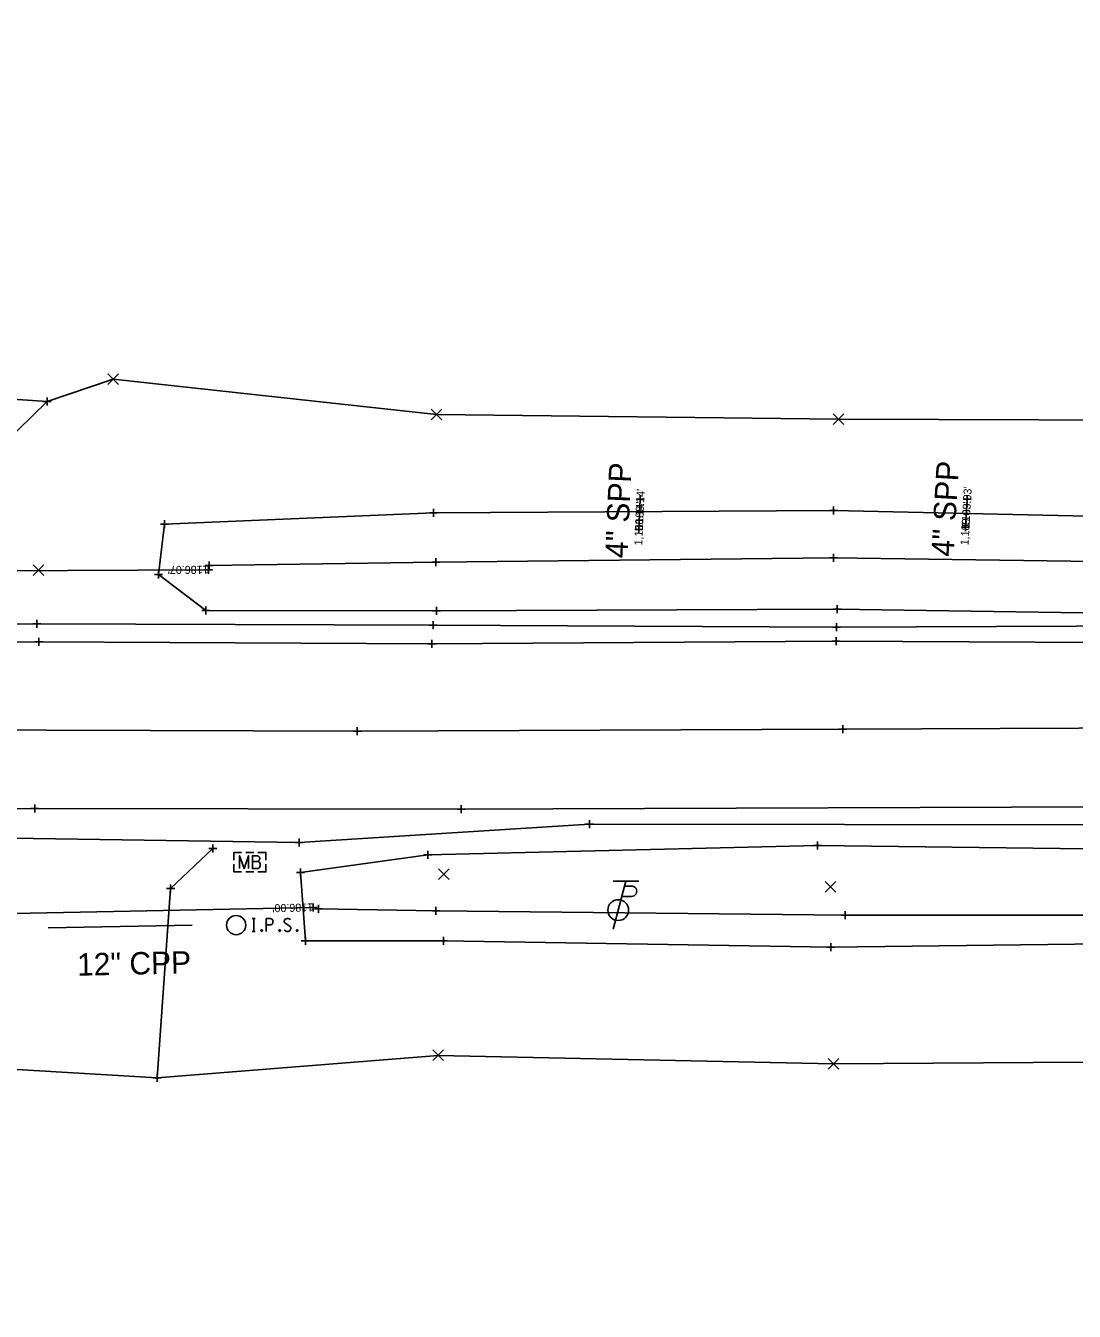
# Model space of a CAD drawing. Extents: x 2319153 to 2321514, y 575338 to 575500.
# Drawn here: x 2320961.9 to 2321092.9, y 575339 to 575499.6 of the extents above; entities that cross this region are included whole.
import ezdxf

# ---------------------------------------------------------------- set-up
doc = ezdxf.new("R2010")
doc.units = 0
for name, color, linetype in [('Default', 7, 'Continuous'), ('DR_X_Ditch', 7, 'Continuous'), ('DR_X_Elev_Flow', 7, 'Continuous'), ('DR_X_Storm_Sewer', 7, 'Continuous'), ('DR_X_Text', 7, 'Continuous'), ('PV_X_COP', 7, 'Continuous'), ('PV_X_Driveway', 7, 'Continuous'), ('PV_X_EOP', 7, 'Continuous'), ('PV_X_Shoulder', 7, 'Continuous'), ('RD_X_Cells', 7, 'Continuous'), ('SC_Scratch1', 7, 'Continuous'), ('SV_P_Mon_Cells_Set', 7, 'Continuous'), ('SV_X_Break_Lines', 7, 'Continuous'), ('SV_X_Random_Point', 7, 'Continuous'), ('SV_X_Shot_Marker', 7, 'Continuous'), ('SV_X_Terrain_Boundary', 7, 'Continuous'), ('UT_X_Misc_Cells', 7, 'Continuous')]:
    doc.layers.add(name, color=color, linetype=linetype)

msp = doc.modelspace()

# ---------------------------------------------------------------- linework, layer by layer
at = {"layer": 'Default'}
for p, q in [((2321038.48, 575436.66), (2321038.48, 575436.66)), ((2321079.27, 575436.97), (2321079.27, 575436.97))]:
    msp.add_line(p, q, dxfattribs=at)
at = {"layer": 'DR_X_Ditch'}
for points in [[(2320984.82, 575432.18), (2321013.13, 575432.58), (2321062.77, 575433.12), (2321113.21, 575432.44), (2321157.3, 575431.05)], [(2321201.56, 575392.03), (2321163.08, 575389.89), (2321113.15, 575388.46), (2321064.26, 575388.47), (2321013.1, 575389.02), (2320998.47, 575389.29)]]:
    msp.add_lwpolyline(points, dxfattribs=at)
at = {"layer": 'DR_X_Elev_Flow'}
for p, q in [((2321038.15, 575440.47), (2321039.15, 575440.47)), ((2321038.65, 575440.97), (2321038.65, 575439.97)), ((2321038.65, 575440.47), (2321038.65, 575440.47)), ((2321078.98, 575440.48), (2321079.98, 575440.48)), ((2321079.48, 575440.98), (2321079.48, 575439.98)), ((2321079.48, 575440.48), (2321079.48, 575440.48)), ((2321037.98, 575436.66), (2321038.98, 575436.66)), ((2321038.48, 575437.16), (2321038.48, 575436.16)), ((2321038.48, 575436.66), (2321038.48, 575436.66)), ((2321078.77, 575436.97), (2321079.77, 575436.97)), ((2321079.27, 575437.47), (2321079.27, 575436.47)), ((2321079.27, 575436.97), (2321079.27, 575436.97)), ((2320984.23, 575431.64), (2320985.23, 575431.64)), ((2320984.73, 575432.14), (2320984.73, 575431.14)), ((2320984.73, 575431.64), (2320984.73, 575431.64)), ((2320997.8, 575389.95), (2320997.8, 575388.95)), ((2320997.3, 575389.45), (2320998.3, 575389.45)), ((2320997.8, 575389.45), (2320997.8, 575389.45))]:
    msp.add_line(p, q, dxfattribs=at)
at = {"layer": 'DR_X_Storm_Sewer'}
for p, q in [((2321038.48, 575436.66), (2321038.65, 575440.47)), ((2321079.27, 575436.97), (2321079.48, 575440.48)), ((2320984.73, 575431.64), (2320820.1, 575430.96)), ((2320997.8, 575389.45), (2320953.53, 575388.55))]:
    msp.add_line(p, q, dxfattribs=at)
at = {"layer": 'DR_X_Text'}
msp.add_line((2320964.71, 575386.88), (2320982.7, 575387.24), dxfattribs=at)
at = {"layer": 'PV_X_COP'}
msp.add_lwpolyline([(2320664.58, 575411.98), (2320714.9, 575412.38), (2320764.67, 575412.55), (2320812.81, 575411.44), (2320863.71, 575412.31), (2320912.72, 575411.78), (2321003.29, 575411.48), (2321063.97, 575411.74), (2321113.08, 575411.94), (2321163.31, 575411.56), (2321212.82, 575411.61), (2321262.91, 575411.78), (2321313.37, 575411.56), (2321362.17, 575411.58), (2321412.59, 575412.78), (2321463.09, 575413.59), (2321512.4, 575413.87)], dxfattribs=at)
at = {"layer": 'PV_X_Driveway'}
for points in [[(2320964.59, 575452.67), (2320949.93, 575438.38), (2320946.04, 575432.42), (2320950.26, 575425.38)], [(2320978.33, 575368.17), (2320980, 575391.82), (2320985.27, 575396.83)]]:
    msp.add_lwpolyline(points, dxfattribs=at)
at = {"layer": 'PV_X_EOP'}
for points in [[(2320664.7, 575422.48), (2320715.11, 575422.41), (2320765.04, 575422.04), (2320813.73, 575422.51), (2320875.77, 575422.41), (2320913.27, 575422.56), (2320963.52, 575422.63), (2321012.62, 575422.4), (2321063.13, 575422.74), (2321112.87, 575422.46), (2321162.94, 575422.5), (2321212.67, 575422.22), (2321263.07, 575422.64), (2321312.9, 575422.52), (2321362.03, 575422.99), (2321412.61, 575423.24), (2321462.61, 575423.66), (2321512.13, 575424.2)], [(2321512.27, 575403.63), (2321462.49, 575403.2), (2321412.87, 575402.74), (2321362.69, 575401.87), (2321312.5, 575402.02), (2321262.43, 575401.63), (2321211.98, 575401.55), (2321107.93, 575402.06), (2321016.27, 575401.73), (2320963.04, 575401.8), (2320913.34, 575401.45), (2320862.76, 575402.1), (2320813.85, 575401.67), (2320764.22, 575401.77), (2320714.4, 575401.87), (2320664.35, 575401.67)]]:
    msp.add_lwpolyline(points, dxfattribs=at)
at = {"layer": 'PV_X_Shoulder'}
for points in [[(2320664.52, 575424.33), (2320715.19, 575424.71), (2320764.98, 575424.15), (2320814.14, 575424.35), (2320863.42, 575424.12), (2320913.2, 575424.6), (2320963.28, 575424.88), (2321012.77, 575424.72), (2321063.18, 575424.45), (2321113.13, 575424.68), (2321162.73, 575424.41), (2321212.81, 575424.31), (2321262.9, 575424.09), (2321312.43, 575424.58), (2321362.34, 575425.06), (2321412.6, 575426.1), (2321462.14, 575426.29), (2321512.24, 575426.46)], [(2321513.03, 575401.02), (2321462.24, 575401.09), (2321412.23, 575401.08), (2321362.25, 575400.75), (2321312.5, 575400.39), (2321262.08, 575400.08), (2321212.3, 575399.81), (2321130.87, 575399.59), (2321095.99, 575399.76), (2321032.33, 575399.84), (2320996.03, 575397.56), (2320957.29, 575398.14), (2320912.73, 575400.28), (2320862.68, 575400.51), (2320815.54, 575400.3), (2320764.25, 575400.14), (2320714.58, 575400.4), (2320664.56, 575400.05)]]:
    msp.add_lwpolyline(points, dxfattribs=at)
at = {"layer": 'RD_X_Cells'}
for p, q in [((2320989.38, 575396.33), (2320990.38, 575396.33)), ((2320989.89, 575395.11), (2320989.89, 575395.11)), ((2320989.38, 575393.89), (2320990.38, 575393.89))]:
    msp.add_line(p, q, dxfattribs=at)
for points in [[(2320987.89, 575395.36), (2320987.89, 575396.33), (2320988.86, 575396.33)], [(2320990.9, 575396.33), (2320991.89, 575396.33), (2320991.89, 575395.36)], [(2320988.86, 575393.89), (2320987.89, 575393.89), (2320987.89, 575394.86)], [(2320988.6, 575394.31), (2320988.6, 575395.91), (2320989.18, 575394.31), (2320989.73, 575395.91), (2320989.73, 575394.31)], [(2320990.91, 575395.18), (2320990.98, 575395.24), (2320991.01, 575395.28), (2320991.04, 575395.32), (2320991.05, 575395.34), (2320991.08, 575395.39), (2320991.09, 575395.43), (2320991.12, 575395.52), (2320991.12, 575395.55), (2320991.12, 575395.61), (2320991.1, 575395.68), (2320991.08, 575395.74), (2320991.04, 575395.79), (2320990.98, 575395.84), (2320990.93, 575395.87), (2320990.9, 575395.88), (2320990.84, 575395.91), (2320990.22, 575395.91), (2320990.22, 575394.31), (2320990.91, 575394.31), (2320991, 575394.36), (2320991.08, 575394.42), (2320991.14, 575394.52), (2320991.18, 575394.63), (2320991.19, 575394.75), (2320991.19, 575394.82), (2320991.17, 575394.9), (2320991.12, 575395.01), (2320991.05, 575395.09), (2320990.91, 575395.18), (2320990.22, 575395.18)], [(2320991.89, 575394.86), (2320991.89, 575393.89), (2320990.9, 575393.89)]]:
    msp.add_lwpolyline(points, dxfattribs=at)
at = {"layer": 'SV_P_Mon_Cells_Set'}
for points in [[(2320990.19, 575388.05), (2320990.55, 575388.05)], [(2320990.37, 575386.45), (2320990.37, 575388.05)], [(2320991.94, 575386.45), (2320991.94, 575388.05), (2320992.47, 575388.05), (2320992.52, 575388.03), (2320992.6, 575388.01), (2320992.63, 575387.98), (2320992.66, 575387.96), (2320992.71, 575387.89), (2320992.74, 575387.83), (2320992.76, 575387.73), (2320992.76, 575387.58), (2320992.75, 575387.53), (2320992.73, 575387.45), (2320992.69, 575387.37), (2320992.64, 575387.33), (2320992.61, 575387.3), (2320992.55, 575387.28), (2320992.47, 575387.26), (2320991.94, 575387.26)], [(2320994.95, 575387.93), (2320994.92, 575387.96), (2320994.89, 575387.98), (2320994.79, 575388.02), (2320994.67, 575388.05), (2320994.58, 575388.05), (2320994.55, 575388.05), (2320994.41, 575388.01), (2320994.28, 575387.93), (2320994.21, 575387.83), (2320994.19, 575387.73), (2320994.19, 575387.66), (2320994.21, 575387.55), (2320994.3, 575387.47), (2320994.9, 575387.09), (2320994.96, 575387.04), (2320994.98, 575386.99), (2320995, 575386.91), (2320995, 575386.84), (2320994.99, 575386.76), (2320994.98, 575386.71), (2320994.96, 575386.65), (2320994.93, 575386.6), (2320994.91, 575386.56), (2320994.88, 575386.52), (2320994.85, 575386.5), (2320994.8, 575386.47), (2320994.77, 575386.46), (2320994.67, 575386.45), (2320994.52, 575386.45), (2320994.42, 575386.47), (2320994.27, 575386.56), (2320994.19, 575386.64)], [(2320990.19, 575386.45), (2320990.55, 575386.45)], [(2320991.33, 575386.66), (2320991.39, 575386.66), (2320991.42, 575386.64), (2320991.45, 575386.58), (2320991.45, 575386.52), (2320991.42, 575386.47), (2320991.39, 575386.45), (2320991.33, 575386.45), (2320991.3, 575386.47), (2320991.26, 575386.52), (2320991.26, 575386.58), (2320991.3, 575386.64), (2320991.33, 575386.66)], [(2320993.58, 575386.66), (2320993.63, 575386.66), (2320993.67, 575386.64), (2320993.7, 575386.58), (2320993.7, 575386.52), (2320993.67, 575386.47), (2320993.63, 575386.45), (2320993.58, 575386.45), (2320993.55, 575386.47), (2320993.51, 575386.52), (2320993.51, 575386.58), (2320993.55, 575386.64), (2320993.58, 575386.66)], [(2320995.76, 575386.66), (2320995.82, 575386.66), (2320995.85, 575386.64), (2320995.88, 575386.58), (2320995.88, 575386.52), (2320995.85, 575386.47), (2320995.82, 575386.45), (2320995.76, 575386.45), (2320995.73, 575386.47), (2320995.7, 575386.52), (2320995.7, 575386.58), (2320995.73, 575386.64), (2320995.76, 575386.66)]]:
    msp.add_lwpolyline(points, dxfattribs=at)
msp.add_circle((2320988.18, 575387.24), 1.2, dxfattribs=at)
at = {"layer": 'SV_X_Break_Lines'}
msp.add_lwpolyline([(2321159.99, 575428.63), (2321160.35, 575434.67), (2321113.2, 575437.94), (2321062.77, 575439.07), (2321012.82, 575438.75), (2320979.25, 575437.35), (2320978.5, 575431.05), (2320984.41, 575426.56), (2321013.21, 575426.53), (2321063.26, 575426.7), (2321113.51, 575425.96), (2321155.53, 575426.35)], close=True, dxfattribs=at)
msp.add_lwpolyline([(2321213.73, 575398.49), (2321160.8, 575396.95), (2321111.27, 575396.57), (2321060.79, 575397.2), (2321012.12, 575396.01), (2320996.2, 575393.81), (2320996.82, 575385.28), (2321014.07, 575385.28), (2321062.46, 575384.49), (2321113.23, 575385.1), (2321161.97, 575386.37), (2321201.76, 575388.95)], dxfattribs=at)
at = {"layer": 'SV_X_Random_Point'}
for p, q in [((2320972.16, 575454.8), (2320973.49, 575456.13)), ((2320972.16, 575456.13), (2320973.49, 575454.8)), ((2321012.53, 575450.36), (2321013.86, 575451.7)), ((2321012.53, 575451.7), (2321013.86, 575450.36)), ((2321062.73, 575449.78), (2321064.06, 575451.12)), ((2321062.73, 575451.12), (2321064.06, 575449.78)), ((2320962.83, 575430.91), (2320964.17, 575432.24)), ((2320962.83, 575432.24), (2320964.17, 575430.91)), ((2321013.47, 575392.95), (2321014.8, 575394.29)), ((2321013.47, 575394.29), (2321014.8, 575392.95)), ((2321061.73, 575391.37), (2321063.07, 575392.7)), ((2321061.73, 575392.7), (2321063.07, 575391.37)), ((2321012.73, 575370.3), (2321014.07, 575371.63)), ((2321012.73, 575371.63), (2321014.07, 575370.3)), ((2321062.13, 575369.25), (2321063.47, 575370.58)), ((2321062.13, 575370.58), (2321063.47, 575369.25))]:
    msp.add_line(p, q, dxfattribs=at)
at = {"layer": 'SV_X_Shot_Marker'}
for p, q in [((2320964.09, 575452.67), (2320965.09, 575452.67)), ((2320964.59, 575453.17), (2320964.59, 575452.17)), ((2320964.59, 575452.67), (2320964.59, 575452.67)), ((2321062.77, 575439.57), (2321062.77, 575438.57)), ((2320979.25, 575437.85), (2320979.25, 575436.85)), ((2321012.32, 575438.75), (2321013.32, 575438.75)), ((2321012.82, 575439.25), (2321012.82, 575438.25)), ((2321012.82, 575438.75), (2321012.82, 575438.75)), ((2321062.27, 575439.07), (2321063.27, 575439.07)), ((2321062.77, 575439.07), (2321062.77, 575439.07)), ((2320978.75, 575437.35), (2320979.75, 575437.35)), ((2320979.25, 575437.35), (2320979.25, 575437.35)), ((2321013.13, 575433.08), (2321013.13, 575432.08)), ((2321062.27, 575433.12), (2321063.27, 575433.12)), ((2321062.77, 575433.62), (2321062.77, 575432.62)), ((2321062.77, 575433.12), (2321062.77, 575433.12)), ((2320978.5, 575431.55), (2320978.5, 575430.55)), ((2320984.32, 575432.18), (2320985.32, 575432.18)), ((2320984.82, 575432.68), (2320984.82, 575431.68)), ((2320984.82, 575432.18), (2320984.82, 575432.18)), ((2321012.63, 575432.58), (2321013.63, 575432.58)), ((2321013.13, 575432.58), (2321013.13, 575432.58)), ((2320978, 575431.05), (2320979, 575431.05)), ((2320978.5, 575431.05), (2320978.5, 575431.05)), ((2320984.41, 575427.06), (2320984.41, 575426.06)), ((2321013.21, 575427.03), (2321013.21, 575426.03)), ((2321062.76, 575426.7), (2321063.76, 575426.7)), ((2321063.26, 575427.2), (2321063.26, 575426.2)), ((2321063.26, 575426.7), (2321063.26, 575426.7)), ((2320963.28, 575425.38), (2320963.28, 575424.38)), ((2320983.91, 575426.56), (2320984.91, 575426.56)), ((2320984.41, 575426.56), (2320984.41, 575426.56)), ((2321012.71, 575426.53), (2321013.71, 575426.53)), ((2321012.77, 575425.22), (2321012.77, 575424.22)), ((2321013.21, 575426.53), (2321013.21, 575426.53)), ((2320962.78, 575424.88), (2320963.78, 575424.88)), ((2320963.28, 575424.88), (2320963.28, 575424.88)), ((2321012.27, 575424.72), (2321013.27, 575424.72)), ((2321012.77, 575424.72), (2321012.77, 575424.72)), ((2321062.68, 575424.45), (2321063.68, 575424.45)), ((2321063.18, 575424.95), (2321063.18, 575423.95)), ((2321063.18, 575424.45), (2321063.18, 575424.45)), ((2320963.02, 575422.63), (2320964.02, 575422.63)), ((2320963.52, 575423.13), (2320963.52, 575422.13)), ((2320963.52, 575422.63), (2320963.52, 575422.63)), ((2321012.12, 575422.4), (2321013.12, 575422.4)), ((2321012.62, 575422.9), (2321012.62, 575421.9)), ((2321012.62, 575422.4), (2321012.62, 575422.4)), ((2321062.63, 575422.74), (2321063.63, 575422.74)), ((2321063.13, 575423.24), (2321063.13, 575422.24)), ((2321063.13, 575422.74), (2321063.13, 575422.74)), ((2321063.97, 575412.24), (2321063.97, 575411.24)), ((2321002.79, 575411.48), (2321003.79, 575411.48)), ((2321003.29, 575411.98), (2321003.29, 575410.98)), ((2321003.29, 575411.48), (2321003.29, 575411.48)), ((2321063.47, 575411.74), (2321064.47, 575411.74)), ((2321063.97, 575411.74), (2321063.97, 575411.74)), ((2320962.54, 575401.8), (2320963.54, 575401.8)), ((2320963.04, 575402.3), (2320963.04, 575401.3)), ((2320963.04, 575401.8), (2320963.04, 575401.8)), ((2321015.77, 575401.73), (2321016.77, 575401.73)), ((2321016.27, 575402.23), (2321016.27, 575401.23)), ((2321016.27, 575401.73), (2321016.27, 575401.73)), ((2321031.83, 575399.84), (2321032.83, 575399.84)), ((2321032.33, 575400.34), (2321032.33, 575399.34)), ((2321032.33, 575399.84), (2321032.33, 575399.84)), ((2320996.03, 575398.06), (2320996.03, 575397.06)), ((2321060.79, 575397.7), (2321060.79, 575396.7)), ((2320984.77, 575396.83), (2320985.77, 575396.83)), ((2320985.27, 575397.33), (2320985.27, 575396.33)), ((2320985.27, 575396.83), (2320985.27, 575396.83)), ((2320995.53, 575397.56), (2320996.53, 575397.56)), ((2320996.03, 575397.56), (2320996.03, 575397.56)), ((2321012.12, 575396.51), (2321012.12, 575395.51)), ((2321060.29, 575397.2), (2321061.29, 575397.2)), ((2321060.79, 575397.2), (2321060.79, 575397.2)), ((2321011.62, 575396.01), (2321012.62, 575396.01)), ((2321012.12, 575396.01), (2321012.12, 575396.01)), ((2320995.7, 575393.81), (2320996.7, 575393.81)), ((2320996.2, 575394.31), (2320996.2, 575393.31)), ((2320996.2, 575393.81), (2320996.2, 575393.81)), ((2320979.5, 575391.82), (2320980.5, 575391.82)), ((2320980, 575392.32), (2320980, 575391.32)), ((2320980, 575391.82), (2320980, 575391.82)), ((2320998.47, 575389.79), (2320998.47, 575388.79)), ((2320997.97, 575389.29), (2320998.97, 575389.29)), ((2320998.47, 575389.29), (2320998.47, 575389.29)), ((2321012.6, 575389.02), (2321013.6, 575389.02)), ((2321013.1, 575389.52), (2321013.1, 575388.52)), ((2321013.1, 575389.02), (2321013.1, 575389.02)), ((2321063.76, 575388.47), (2321064.76, 575388.47)), ((2321064.26, 575388.97), (2321064.26, 575387.97)), ((2321064.26, 575388.47), (2321064.26, 575388.47)), ((2320996.32, 575385.28), (2320997.32, 575385.28)), ((2320996.82, 575385.78), (2320996.82, 575384.78)), ((2320996.82, 575385.28), (2320996.82, 575385.28)), ((2321013.57, 575385.28), (2321014.57, 575385.28)), ((2321014.07, 575385.78), (2321014.07, 575384.78)), ((2321014.07, 575385.28), (2321014.07, 575385.28)), ((2321062.46, 575384.99), (2321062.46, 575383.99)), ((2321061.96, 575384.49), (2321062.96, 575384.49)), ((2321062.46, 575384.49), (2321062.46, 575384.49)), ((2320977.83, 575368.17), (2320978.83, 575368.17)), ((2320978.33, 575368.67), (2320978.33, 575367.67)), ((2320978.33, 575368.17), (2320978.33, 575368.17))]:
    msp.add_line(p, q, dxfattribs=at)
at = {"layer": 'SV_X_Terrain_Boundary'}
for points in [[(2321262.9, 575424.09), (2321213.75, 575454.03), (2321174.26, 575455.72), (2321165.44, 575454.44), (2321113.51, 575450.31), (2321063.39, 575450.45), (2321013.2, 575451.03), (2320972.82, 575455.47), (2320964.59, 575452.67), (2320952.83, 575453.45), (2320913.64, 575458.23), (2320857.66, 575474.67), (2320815.41, 575459.23), (2320777.59, 575499.63), (2320770.49, 575484.86), (2320769.15, 575483.51), (2320759.85, 575485.4), (2320758.6, 575484.73), (2320747.1, 575477.92), (2320738.56, 575481.4), (2320734.01, 575484.3), (2320722.62, 575480.62), (2320707.74, 575483.24), (2320663.9, 575465.47)], [(2320654.2, 575376.01), (2320714.52, 575366.13), (2320764.01, 575354.08), (2320802.52, 575338.98), (2320810.61, 575341.7), (2320812.62, 575342.69), (2320818.49, 575343.02), (2320821.03, 575342.66), (2320862.94, 575355.7), (2320914.29, 575368.22), (2320960.12, 575369.23), (2320978.33, 575368.17), (2321013.4, 575370.96), (2321062.8, 575369.91), (2321112.71, 575370.23), (2321163.35, 575371.72), (2321212.47, 575372.75), (2321262.08, 575400.08)]]:
    msp.add_lwpolyline(points, dxfattribs=at)
at = {"layer": 'UT_X_Misc_Cells'}
for p, q in [((2321036.87, 575392.71), (2321035.26, 575386.71)), ((2321038.47, 575392.71), (2321035.27, 575392.71)), ((2321036.71, 575392.11), (2321037.56, 575392.11)), ((2321036.37, 575390.83), (2321037.56, 575390.83))]:
    msp.add_line(p, q, dxfattribs=at)
msp.add_circle((2321035.9, 575389.11), 1.3, dxfattribs=at)
msp.add_arc((2321037.57, 575391.47), 0.638, 268.8767, 91.1233, dxfattribs=at)

# ---------------------------------------------------------------- texts
at = {"layer": 'DR_X_Text'}
for s, rotation, p in [('4" SPP', 87.4317, (2321037.05, 575433.05)), ('4" SPP', 86.6383, (2321077.78, 575433.23)), ('12" CPP', 1.1633, (2320968.34, 575380.91))]:
    msp.add_text(s, height=2.8, rotation=rotation, dxfattribs=at).set_placement(p)
at = {"layer": 'SC_Scratch1'}
for s, rotation, p in [("1188.14'", 87.4317, (2321038.98, 575436.64)), ("1189.03'", 86.6383, (2321079.77, 575436.94)), ("1,188.14'", 87.4317, (2321038.89, 575434.67)), ("1,189.03'", 86.6383, (2321079.64, 575434.68)), ("1186.07'", 180.2376, (2320984.73, 575432.14)), ("1186.00'", 181.1633, (2320997.79, 575389.95))]:
    msp.add_text(s, height=1, rotation=rotation, dxfattribs=at).set_placement(p)

doc.saveas('drawing.dxf')
